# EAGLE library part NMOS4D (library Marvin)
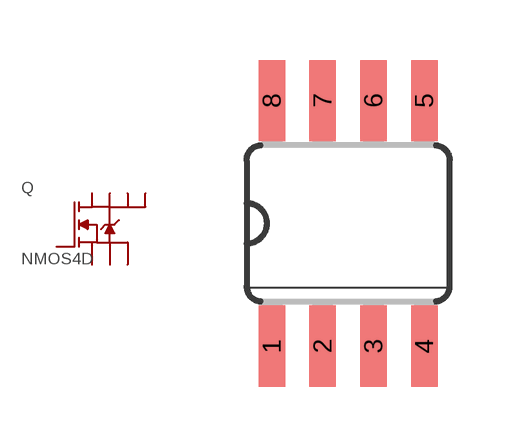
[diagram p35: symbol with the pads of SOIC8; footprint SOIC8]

Designator prefix Q

## NMOS4D  [SOIC8]
1  S1  pas
2  S2  pas
3  S3  pas
4  G  pas
5  D1  pas
6  D2  pas
7  D3  pas
8  D4  pas

## Footprint SOIC8 (pad centres in mm)
smd 0.66 x 2.032: 1 -1.905,-3.073; 2 -0.635,-3.073; 3 0.635,-3.073; 4 1.905,-3.073; 5 1.905,3.073; 6 0.635,3.073; 7 -0.635,3.073; 8 -1.905,3.073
